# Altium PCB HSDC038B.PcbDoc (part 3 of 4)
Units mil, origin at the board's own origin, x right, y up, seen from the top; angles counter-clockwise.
Board outline 3620 x 4060 mil, 6 copper layers (Top Layer, Signal Layer 1, Signal Layer 2, Signal Layer 3, Signal Layer 4, Bottom Layer), stack 60.4 mil thick; 349 components, 209 nets, 1023 pads, 960 vias.
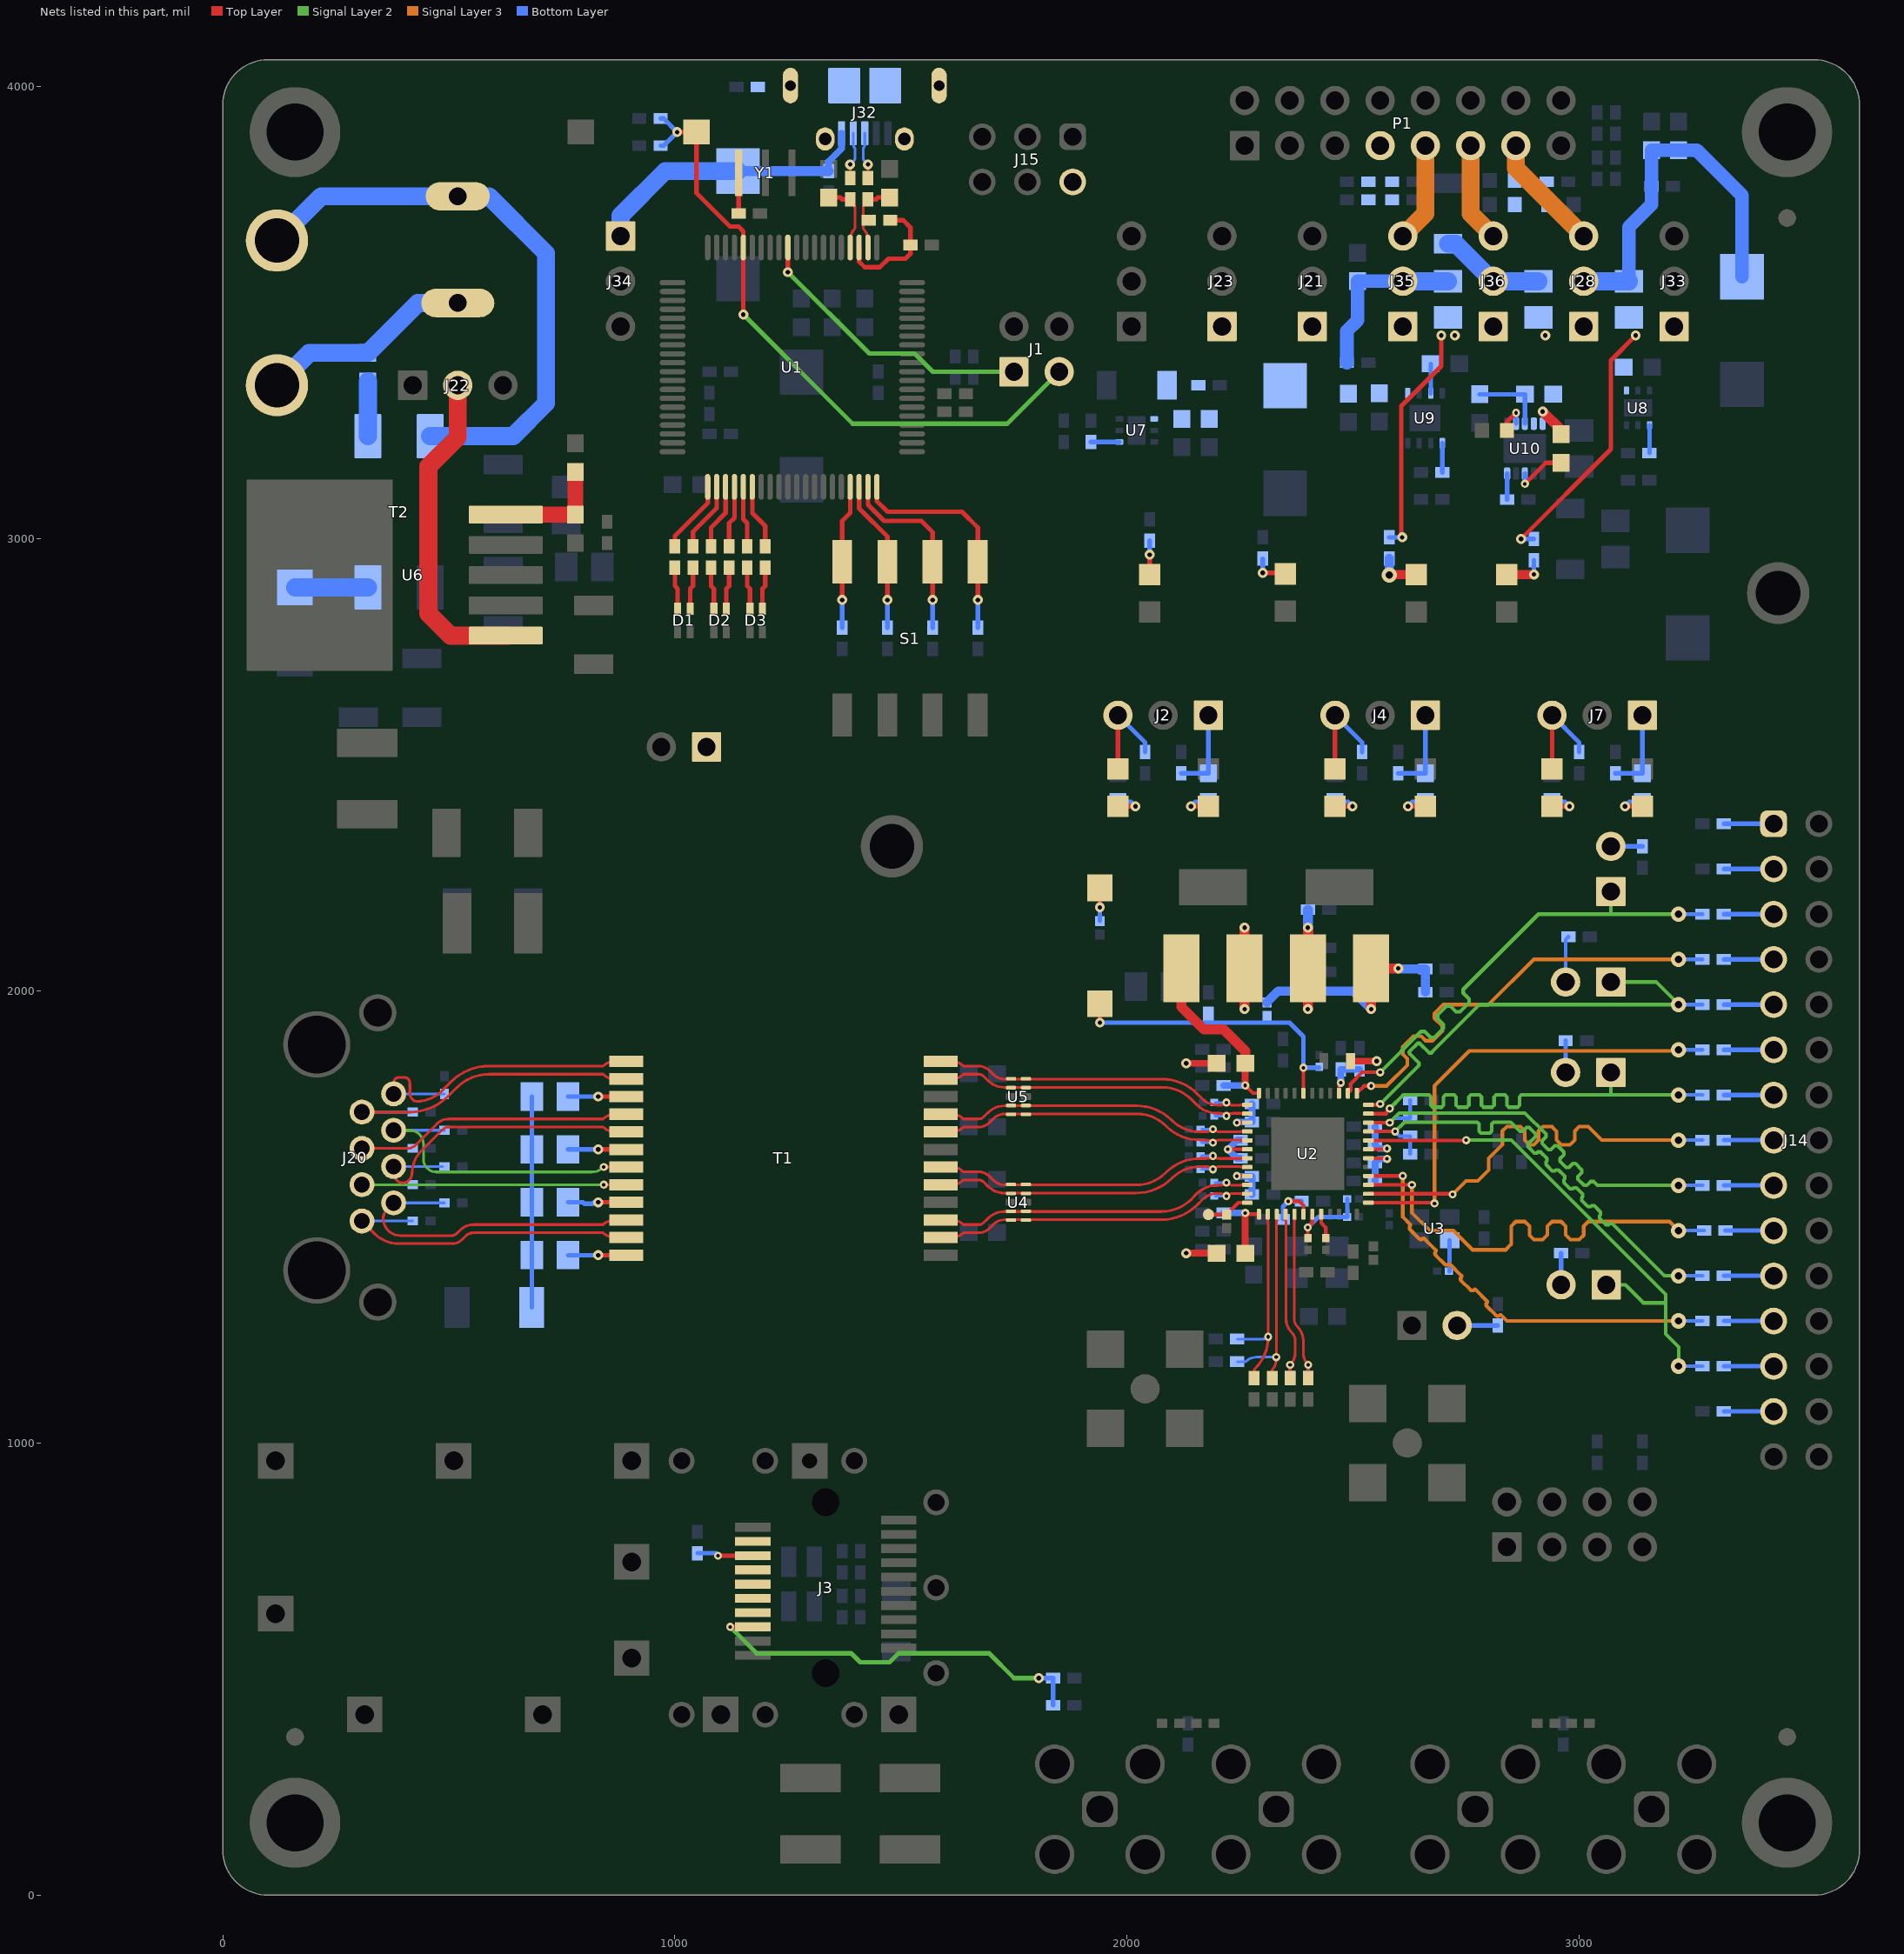
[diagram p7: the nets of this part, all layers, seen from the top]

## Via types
v1: diameter 24, hole 12, Top Layer to Bottom Layer, tented both sides, 728 vias
v2: diameter 22, hole 10, Top Layer to Bottom Layer, tented both sides, 113 vias
v3: diameter 17.87, hole 7.87, Top Layer to Bottom Layer, tented both sides, 67 vias
v4: diameter 19.68, hole 7.87, Top Layer to Bottom Layer, tented both sides, 24 vias
v5: diameter 34, hole 16, Top Layer to Bottom Layer, tented both sides, 15 vias
v6: diameter 18, hole 8, Top Layer to Bottom Layer, tented both sides, 13 vias

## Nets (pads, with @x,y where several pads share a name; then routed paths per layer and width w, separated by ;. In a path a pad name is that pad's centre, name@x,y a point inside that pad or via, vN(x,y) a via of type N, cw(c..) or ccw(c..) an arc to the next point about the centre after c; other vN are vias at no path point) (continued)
NetC59_1: C59.1 R96.1 R97.1 R98.1 R99.1 | length 466.4
  Bottom Layer w10: C59.1@683.61,1300 R99.1@683.61,1415.63 R98.1@683.61,1532.56 R97.1@683.61,1649.49 R96.1@683.61,1766.42
NetC88_2: C88.2 C89.2 C90.2 C91.1 J28.2 R105.1 | length 832.1
  Bottom Layer w30: R105.1@3110,3570 3110,3690 3160,3740 C90.2@3160,3780 C89.2@3160,3860 C88.2@3220,3860 3260,3860 3360,3760 C91.1@3360,3580
  Bottom Layer w40: J28.2@3010,3570 R105.1@3110,3570
NetC98_1: C98.1 C100.2 C101.2 C102.2 J35.2 R111.1 | length 389.8
  Bottom Layer w30: C102.2@2486.38,3390 2486.38,3460 2510,3483.62 C101.2@2510,3570 J35.2@2610,3570
  Bottom Layer w40: J35.2@2610,3570 R111.1@2710,3570
NetC105_2: C105.2 U9.3 | length 64.9
  Bottom Layer w10: U9.3@2671.85,3322.4 C105.2@2671.85,3387.28
NetC110_1: C110.1 C111.1 C112.2 C113.2 C114.2 J36.2 R115.1 | length 234.4
  Bottom Layer w40: C110.1@2710,3653.07 2726.93,3653.07 J36.2@2810,3570 R115.1@2910,3570
NetC118_2: C118.2 U10.7 | length 71.2
  Top Layer w10: C118.2@2840.32,3240 2840.32,3259 v3(2860.32,3279)
  Bottom Layer w10: U10.7@2860.31,3255.12 v3(2860.32,3279)
NetD1_1: D1.1 R2.1 | length 93.4
  Top Layer w10: D1.1@1033.78,2845.59 1033.78,2890 1040,2896.22 R2.1@1040,2936.38
NetD1_2: D1.2 R1.1 | length 93.4
  Top Layer w10: R1.1@1000,2936.38 1000,2896.22 1006.22,2890 D1.2@1006.22,2845.59
NetD2_1: D2.1 R4.1 | length 93.4
  Top Layer w10: D2.1@1113.78,2845.59 1113.78,2890 1120,2896.22 R4.1@1120,2936.38
NetD2_2: D2.2 R3.1 | length 93.4
  Top Layer w10: R3.1@1080,2936.38 1080,2896.22 1086.22,2890 D2.2@1086.22,2845.59
NetD3_1: D3.1 R6.1 | length 93.4
  Top Layer w10: D3.1@1193.78,2845.59 1193.78,2890 1200,2896.22 R6.1@1200,2936.38
NetD3_2: D3.2 R5.1 | length 93.4
  Top Layer w10: R5.1@1160,2936.38 1160,2896.22 1166.22,2890 D3.2@1166.22,2845.59
NetD4_2: D4.2 T2.4 | length 161.1
  Bottom Layer w40: D4.2@160,2892.68 T2.4@321.1,2892.68
NetD5_1: D5.1 R107.1 | length 75.1
  Top Layer w10: D5.1@2050,2921.32 v2(2050,2965)
  Bottom Layer w10: v2(2050,2965) R107.1@2050,2996.38
NetD6_1: D6.1 R108.1 | length 82.3
  Top Layer w10: v2(2300,2924.98) 2347.66,2924.98 D6.1@2350,2922.64
  Bottom Layer w10: v2(2300,2924.98) R108.1@2300,2956.38
NetD7_1: D7.1 R109.1 | length 96.9
  Top Layer w20: v5(2580,2920) 2581.34,2921.34 D7.1@2640,2921.34
  Bottom Layer w20: v5(2580,2920) R109.1@2580,2956.38
NetD8_1: D8.1 R110.1 | length 91.4
  Top Layer w20: D8.1@2840,2921.34 v2(2900,2921.34)
  Bottom Layer w10: v2(2900,2921.34) R110.1@2900,2952.71
NetF1_1: F1.1 J24.1 J25.1 | length 475.3
  Bottom Layer w40: J24.1@120,3340 191.5,3411.5 F1.1@321.1,3411.5 431.5,3521.89 J25.1@520,3521.89
NetF1_2: F1.2 T2.1 | length 121.2
  Bottom Layer w40: T2.1@321.1,3227.32 F1.2@321.1,3348.5
NetJ2_1: J2.1 R20.2 R21.1 | length 188.5
  Bottom Layer w10: R20.2@2120,2481.5 R21.1@2180,2481.5 J2.1@2180,2610
NetJ2_3: J2.3 LD1.2 R19.1 | length 224.8
  Top Layer w10: LD1.2@1980,2491.34 J2.3@1980,2610
  Bottom Layer w10: J2.3@1980,2610 2040,2550 R19.1@2040,2528.74
NetJ4_1: J4.1 R27.2 R28.2 | length 188.5
  Bottom Layer w10: R27.2@2600,2481.5 R28.2@2660,2481.5 J4.1@2660,2610
NetJ4_3: J4.3 LD3.2 R25.1 | length 224.8
  Top Layer w10: LD3.2@2460,2491.34 J4.3@2460,2610
  Bottom Layer w10: J4.3@2460,2610 2520,2550 R25.1@2520,2528.74
NetJ6_2: J6.2 R30.1 | length 70
  Bottom Layer w10: J6.2@2960,1350 R30.1@2960,1420
NetJ7_1: J7.1 R36.2 R37.2 | length 188.5
  Bottom Layer w10: R37.2@3080,2481.5 R36.2@3140,2481.5 J7.1@3140,2610
NetJ7_3: J7.3 LD5.2 R32.1 | length 224.8
  Top Layer w10: LD5.2@2940,2491.34 J7.3@2940,2610
  Bottom Layer w10: J7.3@2940,2610 3000,2550 R32.1@3000,2528.74
NetJ8_2: J8.2 R35.1 | length 70
  Bottom Layer w10: J8.2@3070,2320 R35.1@3140,2320
NetJ10_2: J10.2 R42.1 | length 70
  Bottom Layer w10: J10.2@2970,1820 R42.1@2970,1890
NetJ11_2: J11.2 R44.1 | length 102.6
  Bottom Layer w8: J11.2@2970,2020 2970,2113.62 R44.1@2976.38,2120
NetJ14_1: J14.1 R49.1 | length 110
  Bottom Layer w10: R49.1@3320,2370 J14.1@3430,2370
NetJ14_3: J14.3 R50.1 | length 110
  Bottom Layer w10: R50.1@3320,2270 J14.3@3430,2270
NetJ14_5: J14.5 R51.1 | length 110
  Bottom Layer w10: R51.1@3320,2170 J14.5@3430,2170
NetJ14_7: J14.7 R52.1 | length 110
  Bottom Layer w10: R52.1@3320,2070 J14.7@3430,2070
NetJ14_9: J14.9 R53.1 | length 110
  Bottom Layer w10: R53.1@3320,1970 J14.9@3430,1970
NetJ14_11: J14.11 R54.1 | length 110
  Bottom Layer w10: R54.1@3320,1870 J14.11@3430,1870
NetJ14_13: J14.13 R55.1 | length 110
  Bottom Layer w10: R55.1@3320,1770 J14.13@3430,1770
NetJ14_15: J14.15 R56.1 | length 110
  Bottom Layer w10: R56.1@3320,1670 J14.15@3430,1670
NetJ14_17: J14.17 R57.1 | length 110
  Bottom Layer w10: R57.1@3320,1570 J14.17@3430,1570
NetJ14_19: J14.19 R58.1 | length 106.4
  Bottom Layer w10: R58.1@3323.62,1470 J14.19@3430,1470
NetJ14_21: J14.21 R59.1 | length 110
  Bottom Layer w10: R59.1@3320,1370 J14.21@3430,1370
NetJ14_23: J14.23 R60.1 | length 110
  Bottom Layer w10: R60.1@3320,1270 J14.23@3430,1270
NetJ14_25: J14.25 R61.1 | length 110
  Bottom Layer w10: R61.1@3320,1170 J14.25@3430,1170
NetJ14_27: J14.27 R62.1 | length 110
  Bottom Layer w10: R62.1@3320,1070 J14.27@3430,1070
NetJ19_2: J19.2 R93.1 | length 90
  Bottom Layer w10: J19.2@2730,1260 R93.1@2820,1260
NetJ22_2: J22.2 U6.1 | length 728.2
  Top Layer w40: J22.2@520,3340 520,3225 455,3160 455,2835 503.86,2786.14 U6.1@631.06,2786.14
NetJ25_2: J25.2 J29.1 T2.2 | length 1306.1
  Bottom Layer w40: J29.1@120,3660 218.11,3758.11 J25.2@520,3758.11 588.89,3758.11 715,3632 715,3300 642.32,3227.32 T2.2@458.9,3227.32
NetJ32_6: J32.6 J32.7 J32.8 J32.9 J32.10 J32.11 R112.1
NetLD1_1: LD1.1 R18.2 | length 81.4
  Top Layer w10: LD1.1@1980,2408.66 v2(2018.66,2408.66)
  Bottom Layer w10: R18.2@1980,2418.5 2008.82,2418.5 v2(2018.66,2408.66)
NetLD2_1: LD2.1 R21.2 | length 81.4
  Top Layer w10: v2(2141.34,2408.66) LD2.1@2180,2408.66
  Bottom Layer w10: v2(2141.34,2408.66) 2151.18,2418.5 R21.2@2180,2418.5
NetLD3_1: LD3.1 R24.2 | length 81.4
  Top Layer w10: LD3.1@2460,2408.66 v2(2498.66,2408.66)
  Bottom Layer w10: R24.2@2460,2418.5 2488.82,2418.5 v2(2498.66,2408.66)
NetLD4_1: LD4.1 R28.1 | length 81.4
  Top Layer w10: v2(2621.34,2408.66) LD4.1@2660,2408.66
  Bottom Layer w10: v2(2621.34,2408.66) 2631.18,2418.5 R28.1@2660,2418.5
NetLD5_1: LD5.1 R29.2 | length 81.4
  Top Layer w10: LD5.1@2940,2408.66 v2(2978.66,2408.66)
  Bottom Layer w10: R29.2@2940,2418.5 2968.82,2418.5 v2(2978.66,2408.66)
NetLD6_1: LD6.1 R36.1 | length 81.4
  Top Layer w10: v2(3101.34,2408.66) LD6.1@3140,2408.66
  Bottom Layer w10: v2(3101.34,2408.66) 3111.18,2418.5 R36.1@3140,2418.5
NetR11_1: R11.1 Y1.3 | length 90
  Top Layer w10: R11.1@1141.14,3720 Y1.3@1141.14,3810
NetR80_2: R80.2 S3.2 | length 73
  Top Layer w10: v2(1940,2185) S3.2@1940,2227.95
  Bottom Layer w10: R80.2@1940,2154.96 v2(1940,2185)
NetR87_1: R87.1 U3.1 | length 68.8
  Bottom Layer w10: R87.1@2713.46,1380 U3.1@2713.46,1448.82
NetR96_2: R96.2 T1.15 | length 128.8
  Top Layer w10: v2(830.63,1766.42) T1.15@892.46,1766.42
  Bottom Layer w10: R96.2@763.61,1766.42 v2(830.63,1766.42)
NetR97_2: R97.2 T1.18 | length 128.8
  Top Layer w10: v2(830.63,1649.49) T1.18@892.46,1649.49
  Bottom Layer w10: R97.2@763.61,1649.49 v2(830.63,1649.49)
NetR98_2: R98.2 T1.21 | length 131.6
  Top Layer w10: v2(830.63,1532.56) T1.21@892.46,1532.56
  Bottom Layer w10: R98.2@763.61,1532.56 796.6,1532.56 799.97,1529.19 818.03,1529.19 821.4,1532.56 v2(830.63,1532.56)
NetR99_2: R99.2 T1.24 | length 128.8
  Top Layer w10: v2(830.63,1415.63) T1.24@892.46,1415.63
  Bottom Layer w10: R99.2@763.61,1415.63 v2(830.63,1415.63)
NetR102_1: R102.1 R103.2 U6.5 | length 248.6
  Top Layer w35: U6.5@626.06,3053.86 R102.1@780,3053.86 R103.2@780,3148.5
NetR104_1: R104.1 U7.4 | length 63.2
  Bottom Layer w10: R104.1@1920,3214.41 U7.4@1983.23,3214.41
NetR106_1: R106.1 U8.4 | length 61.6
  Bottom Layer w10: R106.1@3155.59,3190 U8.4@3155.59,3251.61
NetR113_1: R113.1 U9.5 | length 64.9
  Bottom Layer w10: R113.1@2697.44,3147.28 U9.5@2697.44,3212.17
NetR114_2: R114.2 U10.3 | length 122.1
  Top Layer w10: v3(2880,3122) 2926.5,3168.5 R114.2@2960,3168.5
  Bottom Layer w10: v3(2880,3122) U10.3@2880,3144.88
NetR116_2: R116.2 U10.5 | length 58
  Bottom Layer w10: R116.2@2840.63,3086.93 U10.5@2840.63,3144.88
NetR117_1: R117.1 R120.2 U10.8 | length 164.9
  Bottom Layer w10: R120.2@2780,3320 R117.1@2880,3320 U10.8@2880,3255.12
P1.0: R1.2 U1.21 | length 161.8
  Top Layer w10: R1.2@1000,2983.62 1000,3006.81 1072.76,3079.57 U1.21@1072.76,3115.24
P1.1: R2.2 U1.22 | length 153.3
  Top Layer w10: R2.2@1040,2983.62 1040,3015.74 1092.44,3068.19 U1.22@1092.44,3115.24
P1.2: R3.2 U1.23 | length 144.9
  Top Layer w10: R3.2@1080,2983.62 1080,3025 1112.13,3057.13 U1.23@1112.13,3115.24
P1.3: R4.2 U1.24 | length 136.5
  Top Layer w10: R4.2@1120,2983.62 1120,3035 1131.81,3046.81 U1.24@1131.81,3115.24
P1.4: R5.2 U1.25 | length 135.1
  Top Layer w10: U1.25@1151.5,3115.24 1151.5,3043.5 1160,3035 R5.2@1160,2983.62
P1.5: R6.2 U1.26 | length 143.6
  Top Layer w10: U1.26@1171.18,3115.24 1171.18,3057.32 1200,3028.5 R6.2@1200,2983.62
RBIAS: R73.2 TP7.1 U2.12 | length 97
  Top Layer w8: TP7.1@2180,1505.45 R73.2@2220,1505.45 2246.28,1531.73 U2.12@2266.14,1531.73
RESET_N: R77.1 R82.2 R83.2 S3.1 U2.43 | length 665
  Top Layer w8: U2.43@2390.16,1773.86 v3(2390.16,1830.31)
  Top Layer w10: v2(1940,1930) S3.1@1940,1972.05
  Bottom Layer w10: v2(1940,1930) 2359.07,1930 2390.16,1898.91 v3(2390.16,1830.31) R83.2@2425,1830.31
RST/SBWTDIO: C1.2 J1.3 R12.2 S2.2 U1.76 | length 1444.3
  Top Layer w10: v2(1005,3900) S2.2@1047.95,3900 1047.95,3765.05 1122,3691 1141,3691 1151.5,3680.5 U1.76@1151.5,3644.76 v2(1151.5,3496.5)
  Signal Layer 2 w10: v2(1151.5,3496.5) 1393,3255 1735,3255 J1.3@1850,3370
  Bottom Layer w10: R12.2@968.62,3870 975,3870 v2(1005,3900) 975,3930 C1.2@968.62,3930
RX_CLK: J6.1 R61.2 U2.32 | length 1169.4
  Top Layer w8: U2.32@2533.86,1669.53 v6@2749.53,1669.53
  Signal Layer 2 w8: v6(2750,1670) 2850,1670 3191.13,1328.87 3191.13,1310 ; J6.1@3060,1350 3102.43,1350 3142.43,1310 3191.13,1310 ; v5(3220,1170) 3220,1212.25 3191.13,1241.13 3191.13,1310
  Bottom Layer w8: v5(3220,1170) R61.2@3272.76,1170
RX_CTRL: J8.1 R51.2 U2.38 | length 1108
  Top Layer w8: U2.38@2488.58,1773.86 2494.53,1779.8 2494.53,1794.53 2520,1820 v6(2560,1820)
  Signal Layer 2 w8: v6(2560,1820) 2650.19,1910.19 2658.68,1910.19 2671.41,1897.47 2679.89,1897.47 2699.69,1917.26 2699.69,1925.75 2686.96,1938.48 2686.96,1946.96 2706.76,1966.76 2715.25,1966.76 2727.98,1954.03 2736.46,1954.03 2756.26,1973.83 2756.26,1982.32 2743.53,1995.05 2743.53,2003.53 2910,2170 3070,2170 ; J8.1@3076.5,2213.5 J8.1@3070,2220 3070,2170 ; v5(3220,2170) 3070,2170
  Bottom Layer w8: v5(3220,2170) R51.2@3272.76,2170
RX_D0: R33.1 R41.2 R59.2 U2.33 | length 1104
  Top Layer w8: U2.33@2533.86,1689.21 v3(2593,1689.21)
  Signal Layer 2 w8: v3(2593,1689.21) 2613.68,1709.9 2774.33,1709.9 2778.53,1705.7 2778.53,1690.07 2782.73,1685.87 2802.33,1685.87 2806.53,1690.07 2806.53,1705.7 2810.73,1709.9 2848.53,1709.9 2869.14,1689.28 2875.08,1689.28 2883.7,1697.91 2889.64,1697.91 2903.5,1684.05 2903.5,1678.11 2886.89,1661.5 2886.89,1655.56 2900.75,1641.7 2906.69,1641.7 2908.74,1643.75 2914.68,1643.75 2928.54,1629.89 2928.54,1623.95 2926.49,1621.9 2926.49,1615.96 2940.35,1602.1 2946.29,1602.1 2948.34,1604.15 2954.28,1604.15 2968.14,1590.29 2968.14,1584.35 2966.09,1582.3 2966.09,1576.36 2979.95,1562.5 2985.89,1562.5 2987.93,1564.55 2993.87,1564.55 3007.73,1550.69 3007.73,1544.75 3005.68,1542.7 3005.68,1536.76 3019.54,1522.9 3025.48,1522.9 3027.53,1524.95 3033.47,1524.95 3047.33,1511.09 3047.33,1505.15 3045.28,1503.1 3045.28,1497.16 3059.14,1483.31 3065.08,1483.31 3067.13,1485.35 3073.07,1485.35 3188.43,1370 v5(3220,1370)
  Bottom Layer w8: v3(2593,1689.21) 2603,1679.21 R33.1@2626.38,1679.21 R41.2@2626.38,1639.21 ; v5(3220,1370) R59.2@3272.76,1370
RX_D1: R40.1 R43.2 R57.2 U2.34 | length 997.5
  Top Layer w8: U2.34@2533.86,1708.9 v3(2581,1708.9)
  Signal Layer 2 w8: v3(2581,1708.9) 2602.1,1730 2880,1730 2926.53,1683.47 2926.53,1677.53 2917.9,1668.91 2917.9,1662.97 2931.76,1649.11 2937.7,1649.11 2946.33,1657.73 2952.27,1657.73 2966.13,1643.87 2966.13,1637.93 2957.5,1629.31 2957.5,1623.37 2971.36,1609.51 2977.3,1609.51 2985.92,1618.14 2991.86,1618.14 3005.72,1604.28 3005.72,1598.34 2997.1,1589.71 2997.1,1583.77 3010.96,1569.91 3016.9,1569.91 3025.52,1578.54 3031.46,1578.54 3040,1570 v5(3220,1570)
  Bottom Layer w8: v3(2581,1708.9) 2591,1718.9 R40.1@2626.38,1718.9 R43.2@2626.38,1758.9 ; v5(3220,1570) R57.2@3272.76,1570
RX_D2: J10.1 R55.2 U2.35 | length 989
  Top Layer w8: U2.35@2533.86,1728.58 2573.58,1728.58 2573.58,1732.58 v6(2581,1740)
  Signal Layer 2 w8: v6@2581,1736 v6(2581,1740) 2611,1770 2667.8,1770 2672,1765.8 2672,1747.2 2676.2,1743 2695.8,1743 2700,1747.2 2700,1765.8 2704.2,1770 2723.8,1770 2728,1765.8 2728,1747.2 2732.2,1743 2751.8,1743 2756,1747.2 2756,1765.8 2760.2,1770 2779.8,1770 2784,1765.8 2784,1747.2 2788.2,1743 2807.8,1743 2812,1747.2 2812,1765.8 2816.2,1770 2835.8,1770 2840,1765.8 2840,1747.2 2844.2,1743 2863.8,1743 2868,1747.2 2868,1765.8 2872.2,1770 3070,1770 ; J10.1@3070,1820 3070,1770 ; v5(3220,1770) 3070,1770
  Bottom Layer w8: v5(3220,1770) R55.2@3272.76,1770
RX_D3: J11.1 R53.2 U2.36 | length 1066.4
  Top Layer w8: U2.36@2533.86,1748.27 2558.27,1748.27 v6(2560,1750)
  Signal Layer 2 w8: v6(2560,1750) 2644.78,1834.78 ccw(c2641.39,1838.18) 2644.79,1841.56 2625.76,1860.59 cw(c2629.16,1863.99) 2625.76,1867.38 2641.6,1883.22 ; 2641.61,1883.23 cw(c2645,1879.82) 2648.38,1883.23 ; 2648.39,1883.22 2667.41,1864.2 ccw(c2670.8,1867.59) 2674.19,1864.19 2780,1970 v5(3220,1970) 3170,2020 J11.1@3070,2020
  Bottom Layer w8: v5(3220,1970) R53.2@3272.76,1970
SFP_LOS: J3.8 R22.1 R23.2 | length 887.5
  Top Layer w10: v3(1122.36,593.39) J3.8@1172.28,593.39
  Signal Layer 2 w10: v3(1122.36,593.39) 1180.75,535 1390,535 1410,515 1475,515 1495,535 1695,535 1750,480 v2(1805,480)
  Bottom Layer w10: v2(1805,480) R22.1@1836.38,480 R23.2@1836.38,420
SFP_MD_0: J3.6
SFP_MD_1: J3.5
SFP_MD_2: J3.4
SFP_RS: J3.7
SFP_TX_DISABLE: J3.3 R26.2 | length 124.6
  Top Layer w10: v6(1095.51,750.87) J3.3@1172.28,750.87
  Bottom Layer w10: R26.2@1050,756.38 1090,756.38 v6(1095.51,750.87)
SFP_TX_FAULT: J3.2
SGMII_SI_N: C15.2 R45.1 U2.17 | length 400.6
  Top Layer w6: U2.17@2370.47,1506.14 2370.47,1492.52 cw(c2367.6,1492.52) 2369.63,1490.49 2369.63,1274.86 ccw(c2393.86,1274.86) 2376.73,1257.73 cw(c2345.2,1226.2) 2389.79,1226.2 2389.79,1199.66 ccw(c2427.34,1199.66) v3(2400.79,1173.1) C15.2@2400.79,1143.62
  Bottom Layer w6: R45.1@2400.79,1143.62 v3(2400.79,1173.1)
SGMII_SI_P: C17.2 R47.1 U2.16 | length 400.6
  Top Layer w6: U2.16@2350.79,1506.14 2350.79,1492.52 ccw(c2353.66,1492.52) 2351.63,1490.49 2351.63,1274.86 ccw(c2393.86,1274.86) 2364,1245 cw(c2345.2,1226.2) 2371.79,1226.2 2371.79,1199.66 cw(c2334.23,1199.66) v3(2360.79,1173.1) C17.2@2360.79,1143.62
  Bottom Layer w6: R47.1@2360.79,1143.62 v3(2360.79,1173.1)
SGMII_SO_N: C12.2 R31.1 U2.14 | length 441.2
  Top Layer w6: C12.2@2281.1,1143.62 2281.1,1159.73 cw(c2287.48,1159.73) 2282.97,1164.24 ccw(c2212.26,1234.95) v6(2312.26,1234.95) 2312.26,1490.49 2311.42,1491.33 U2.14@2311.42,1506.14
  Bottom Layer w6: R31.1@2243.62,1230 2300.31,1230 ccw(c2300.31,1246.9) v6(2312.26,1234.95)
SGMII_SO_P: C14.2 R38.1 U2.15 | length 454.4
  Top Layer w6: C14.2@2321.1,1143.62 2321.1,1162.37 ccw(c2298.99,1184.48) 2330.26,1184.48 2330.26,1490.49 2331.1,1491.33 U2.15@2331.1,1506.14
  Bottom Layer w6: R38.1@2243.62,1180 2262.37,1180 cw(c2286.51,1155.86) 2286.51,1190 v6(2330,1190)
SW_1: R10.2 S1.4 U1.37 | length 319
  Top Layer w10: v2(1370,2865) S1.4@1370,2949.5 1370,3040 1387.72,3057.72 U1.37@1387.72,3115.24
  Bottom Layer w10: R10.2@1370,2803.62 v2(1370,2865)
SW_2: R9.2 S1.3 U1.38 | length 337.5
  Top Layer w10: U1.38@1407.4,3115.24 1407.4,3067.6 1470,3005 S1.3@1470,2949.5 v2(1470,2865)
  Bottom Layer w10: R9.2@1470,2803.62 v2(1470,2865)
SW_3: R8.2 S1.2 U1.39 | length 419
  Top Layer w10: U1.39@1427.09,3115.24 1427.09,3075.63 1462.72,3040 1545,3040 1570,3015 S1.2@1570,2949.5 v2(1570,2865)
  Bottom Layer w10: R8.2@1570,2803.62 v2(1570,2865)
SW_4: R7.2 S1.1 U1.40 | length 500.5
  Top Layer w10: U1.40@1446.77,3115.24 1446.77,3083.54 1470.31,3060 1635,3060 1670,3025 S1.1@1670,2949.5 v2(1670,2865)
  Bottom Layer w10: R7.2@1670,2803.62 v2(1670,2865)
TARGET_D_N: C11.2 R16.1 U1.64 | length 162
  Top Layer w6: U1.64@1387.72,3644.76 1387.72,3661.2 cw(c1424.2,3661.2) 1398.4,3686.99 1398.4,3729.82 ccw(c1372.17,3729.82) 1390.72,3748.38 R16.1@1387.72,3751.38
  Top Layer w10: C11.2@1340.2,3755.49 1365.71,3755.49 1369.82,3751.38 R16.1@1387.72,3751.38
TARGET_D_P: C10.2 R13.2 R17.1 U1.62 | length 162
  Top Layer w6: U1.62@1427.09,3644.76 1427.09,3661.2 ccw(c1390.61,3661.2) 1416.4,3686.99 1416.4,3729.82 cw(c1442.64,3729.82) 1424.09,3748.38 R17.1@1427.09,3751.38
  Top Layer w10: R17.1@1427.09,3751.38 1444.99,3751.38 1449.09,3755.49 C10.2@1474.61,3755.49
TARGET_PUR: R13.1 R14.1 U1.63 | length 271.9
  Top Layer w10: U1.63@1407.4,3644.76 1407.4,3613.6 1420,3601 1453.4,3601 1472.4,3620 1510.2,3620 1520.91,3630.71 R14.1@1520.91,3650 1520.91,3689.29 1505.2,3705 R13.1@1476.33,3705
TD_A_N: R64.1 T1.11 U2.2 U5.2 U5.9 | length 736
  Top Layer w6: T1.11@1587.54,1805.39 1613.21,1805.39 ccw(c1613.21,1841.2) 1638.53,1815.88 1671.74,1815.88 cw(c1671.74,1799.58) 1683.27,1811.11 1692.37,1802.01 ccw(c1728.6,1838.23) 1728.6,1787 2077.75,1787 cw(c2077.75,1695.75) 2142.27,1760.27 2154.11,1748.43 ccw(c2200,1794.32) 2200,1729.43 2205.89,1729.43 cw(c2205.89,1709.48) v3(2220,1723.58) cw(c2234.11,1709.48) 2234.11,1729.43 2250.49,1729.43 ccw(c2252.52,1731.46) 2252.52,1728.58 U2.2@2266.14,1728.58
  Bottom Layer w6: R64.1@2194.96,1723.58 v3(2220,1723.58)
TD_A_P: R63.1 T1.12 U2.1 U5.1 U5.10 | length 736
  Top Layer w6: T1.12@1587.54,1844.37 1613.21,1844.37 cw(c1613.21,1808.56) 1638.53,1833.88 1671.74,1833.88 cw(c1671.74,1799.58) 1696,1823.83 1705.1,1814.73 ccw(c1728.6,1838.23) 1728.6,1805 2077.75,1805 cw(c2077.75,1695.75) 2155,1773 2166.84,1761.16 ccw(c2200,1794.32) 2200,1747.43 2205.89,1747.43 ccw(c2205.89,1767.37) v3(2220,1753.27) ccw(c2234.11,1767.37) 2234.11,1747.43 2250.49,1747.43 cw(c2252.52,1745.39) 2252.52,1748.27 U2.1@2266.14,1748.27
  Bottom Layer w6: R63.1@2194.96,1753.27 v3(2220,1753.27)
TD_B_N: R66.1 T1.8 U2.5 U5.5 U5.6 | length 734.3
  Top Layer w6: T1.8@1587.54,1688.46 1613.21,1688.46 ccw(c1613.21,1724.27) 1638.53,1698.95 1671.74,1698.95 ccw(c1671.74,1733.26) 1696,1709 1705.1,1718.1 cw(c1729,1694.2) 1729,1728 2021.75,1728 cw(c2021.75,1636.75) 2086.27,1701.27 ccw(c2160.88,1775.88) 2160.88,1670.37 2175.89,1670.37 cw(c2175.89,1650.42) v3(2190,1664.53) cw(c2204.11,1650.42) 2204.11,1670.37 2250.49,1670.37 ccw(c2252.52,1672.4) 2252.52,1669.53 U2.5@2266.14,1669.53
  Bottom Layer w6: R66.1@2164.96,1664.53 v3(2190,1664.53)
TD_B_P: R65.1 T1.9 U2.4 U5.4 U5.7 | length 734.3
  Top Layer w6: T1.9@1587.54,1727.44 1613.21,1727.44 cw(c1613.21,1691.63) 1638.53,1716.95 1671.74,1716.95 ccw(c1671.74,1733.26) 1683.27,1721.73 1692.37,1730.83 cw(c1729,1694.2) 1729,1746 2021.75,1746 cw(c2021.75,1636.75) 2099,1714 ccw(c2160.88,1775.88) 2160.88,1688.37 2175.89,1688.37 ccw(c2175.89,1708.32) v3(2190,1694.21) ccw(c2204.11,1708.32) 2204.11,1688.37 2250.49,1688.37 cw(c2252.52,1686.34) 2252.52,1689.21 U2.4@2266.14,1689.21
  Bottom Layer w6: R65.1@2164.96,1694.21 v3(2190,1694.21)
TD_C_N: R68.1 T1.5 U2.8 U4.2 U4.9 | length 734.5
  Top Layer w6: T1.5@1587.54,1571.54 1613.21,1571.54 ccw(c1613.21,1607.34) 1638.53,1582.02 1671.74,1582.02 cw(c1671.74,1565.72) 1683.27,1577.25 1692.37,1568.15 ccw(c1728.94,1604.72) 1728.94,1553 2020.09,1553 ccw(c2020.09,1664.59) 2099,1585.69 cw(c2160.88,1523.81) 2160.88,1611.32 2175.89,1611.32 cw(c2175.89,1591.37) v3(2190,1605.47) cw(c2204.11,1591.37) 2204.11,1611.32 2250.49,1611.32 ccw(c2252.52,1613.35) 2252.52,1610.47 U2.8@2266.14,1610.47
  Bottom Layer w6: R68.1@2164.96,1605.47 v3(2190,1605.47)
TD_C_P: R67.1 T1.6 U2.7 U4.1 U4.10 | length 734.5
  Top Layer w6: T1.6@1587.54,1610.51 1613.21,1610.51 cw(c1613.21,1574.7) 1638.53,1600.02 1671.74,1600.02 cw(c1671.74,1565.72) 1696,1589.98 1705.1,1580.88 ccw(c1728.94,1604.72) 1728.94,1571 2020.09,1571 ccw(c2020.09,1664.59) 2086.27,1598.41 cw(c2160.88,1523.81) 2160.88,1629.32 2175.89,1629.32 ccw(c2175.89,1649.26) v3(2190,1635.16) ccw(c2204.11,1649.26) 2204.11,1629.31 2250.49,1629.32 cw(c2252.52,1627.28) 2252.52,1630.16 U2.7@2266.14,1630.16
  Bottom Layer w6: R67.1@2164.96,1635.16 v3(2190,1635.16)
TD_D_N: R70.1 T1.2 U2.11 U4.5 U4.6 | length 736.2
  Top Layer w6: T1.2@1587.54,1454.61 1613.21,1454.61 ccw(c1613.21,1490.42) 1638.53,1465.09 1671.74,1465.09 ccw(c1671.74,1499.4) 1696,1475.14 1705.1,1484.24 cw(c1728.66,1460.69) 1728.66,1494 2076.09,1494 ccw(c2076.09,1605.59) 2155,1526.69 2166.84,1538.52 cw(c2200,1505.36) 2200,1552.26 2205.89,1552.26 cw(c2205.89,1532.31) v3(2220,1546.42) cw(c2234.11,1532.31) 2234.11,1552.26 2250.49,1552.26 ccw(c2252.52,1554.29) 2252.52,1551.42 U2.11@2266.14,1551.42
  Bottom Layer w6: R70.1@2194.96,1546.42 v3(2220,1546.42)
TD_D_P: R69.1 T1.3 U2.10 U4.4 U4.7 | length 736.2
  Top Layer w6: T1.3@1587.54,1493.58 1613.21,1493.58 cw(c1613.21,1457.77) 1638.53,1483.09 1671.74,1483.09 ccw(c1671.74,1499.4) 1683.27,1487.87 1692.37,1496.97 cw(c1728.66,1460.69) 1728.66,1512 2076.09,1512 ccw(c2076.09,1605.59) 2142.27,1539.41 2154.11,1551.25 cw(c2200,1505.36) 2200,1570.26 2205.89,1570.26 ccw(c2205.89,1590.21) v3(2220,1576.1) ccw(c2234.11,1590.21) 2234.11,1570.26 2250.49,1570.26 cw(c2252.52,1568.23) 2252.52,1571.1 U2.10@2266.14,1571.1
  Bottom Layer w6: R69.1@2194.96,1576.1 v3(2220,1576.1)
TEST/SBWTCK: J1.1 U1.71 | length 646
  Top Layer w10: v2(1249.92,3590.08) U1.71@1249.92,3644.76
  Signal Layer 2 w10: v2(1249.92,3590.08) 1430,3410 1530.32,3410 1570.32,3370 J1.1@1750,3370
  Bottom Layer w10: v2(1249.92,3590.08) v2@1250,3590
TP_CH1_N: C56.1 J20.7 T1.14 | length 725
  Top Layer w6: J20.7@307.91,1732.17 414.74,1732.17 ccw(c414.74,1850.17) 498.18,1766.72 518.05,1786.59 cw(c588.76,1715.88) 588.76,1815.88 841.47,1815.88 ccw(c866.79,1841.2) 866.79,1805.39 T1.14@892.46,1805.39
  Bottom Layer w6: J20.7@307.91,1732.17 C56.1@420.32,1732.17
TP_CH1_P: C58.1 J20.8 T1.13 | length 725.3
  Top Layer w6: J20.8@377.99,1772.32 377.99,1796.5 cw(c390.5,1796.5) 390.5,1809 401.5,1809 cw(c401.5,1796.5) 414,1796.5 414,1773.33 ccw(c432.16,1773.33) 426.99,1755.92 428.63,1755.92 ccw(c428.63,1836.28) 485.45,1779.45 505.33,1799.33 cw(c588.76,1715.88) 588.76,1833.88 841.47,1833.88 cw(c866.79,1808.56) 866.79,1844.37 T1.13@892.46,1844.37
  Bottom Layer w6: J20.8@377.99,1772.32 C58.1@490.39,1772.32
TP_CH2_N: C53.1 J20.4 T1.17 | length 720.1
  Top Layer w6: J20.4@377.99,1611.69 377.99,1596.37 ccw(c398.35,1596.37) 398.35,1576.02 ccw(c398.35,1596.37) 418.7,1596.37 cw(c489.52,1596.37) 439.45,1646.45 486.26,1693.26 cw(c500,1679.52) 500,1698.95 841.47,1698.95 ccw(c866.79,1724.27) 866.79,1688.46 T1.17@892.46,1688.46
  Bottom Layer w6: J20.4@377.99,1611.69 C53.1@486.46,1611.69
TP_CH2_P: C55.1 J20.5 T1.16 | length 720.1
  Top Layer w6: J20.5@307.91,1651.85 408.67,1651.85 ccw(c408.67,1677.74) 426.98,1659.43 473.53,1705.99 cw(c500,1679.52) 500,1716.95 841.47,1716.95 cw(c866.79,1691.63) 866.79,1727.44 T1.16@892.46,1727.44
  Bottom Layer w6: J20.5@307.91,1651.85 C55.1@416.38,1651.85
TP_CH3_N: C50.1 J20.3 T1.20 | length 696.9
  Top Layer w6: v3(842.72,1571.54) T1.20@892.46,1571.54
  Signal Layer 2 w6: J20.3@307.91,1571.54 v3(842.72,1571.54)
  Bottom Layer w6: J20.3@307.91,1571.54 C50.1@420.32,1571.54
TP_CH3_P: C52.1 J20.6 T1.19 | length 697
  Top Layer w6: v3(842.72,1610.51) T1.19@892.46,1610.51
  Signal Layer 2 w6: J20.6@377.99,1692.01 413.26,1692.01 cw(c413.26,1661.27) 444,1661.27 444,1627.65 ccw(c472.12,1627.65) 472.12,1599.52 816.19,1599.52 ccw(c816.19,1637.04) v3(842.72,1610.51)
  Bottom Layer w6: J20.6@377.99,1692.01 C52.1@490.39,1692.01
TP_CH4_N: C47.1 J20.1 T1.23 | length 724.9
  Top Layer w6: J20.1@307.91,1491.22 335.9,1463.24 ccw(c389.58,1516.92) 389.58,1441 507.1,1441 ccw(c507.1,1473.24) 529.9,1450.44 537.73,1458.27 cw(c554.2,1441.8) 554.2,1465.09 841.47,1465.09 ccw(c866.79,1490.42) 866.79,1454.61 T1.23@892.46,1454.61
  Bottom Layer w6: J20.1@307.91,1491.22 C47.1@420.32,1491.22
TP_CH4_P: C48.1 J20.2 T1.22 | length 724.7
  Top Layer w6: J20.2@377.99,1531.38 363.05,1516.44 ccw(c382.49,1497) 355,1497 ccw(c393,1497) 393,1459 507.1,1459 ccw(c507.1,1473.24) 517.17,1463.17 525,1471 cw(c554.2,1441.8) 554.2,1483.09 841.47,1483.09 cw(c866.79,1457.77) 866.79,1493.58 T1.22@892.46,1493.58
  Bottom Layer w6: J20.2@377.99,1531.38 C48.1@490.39,1531.38
TX_CTRL: R52.2 U2.37 | length 980.6
  Top Layer w8: U2.37@2508.27,1773.86 2524.41,1790 v6(2540,1790)
  Signal Layer 3 w8: v6(2540,1790) 2574.16,1790 2620,1835.84 2620,1850 2610,1860 2610,1876.61 2633.39,1900 2650.38,1900 2660.38,1890 2675.8,1890 2697.5,1911.7 2697.5,1922.5 2680,1940 2680,1950 2700,1970 2800,1970 2900,2070 v5(3220,2070)
  Bottom Layer w8: v5(3220,2070) R52.2@3272.76,2070
TX_D0: R60.2 U2.28 | length 962.6
  Top Layer w8: U2.28@2533.86,1590.79 v6(2610,1590.79)
  Signal Layer 3 w8: v6(2610,1590.79) 2610,1500 2626.3,1483.7 cw(c2624.74,1482.13) 2626.3,1480.57 ccw(c2630.54,1476.32) 2626.3,1472.08 2646.1,1452.28 ccw(c2650.34,1456.52) 2654.59,1452.28 cw(c2656.15,1450.72) 2657.71,1452.29 2682.87,1427.13 ; 2682.88,1427.12 cw(c2681.3,1425.56) 2682.87,1424 ccw(c2687.11,1419.75) 2682.87,1415.51 2702.67,1395.71 ccw(c2706.91,1399.96) 2711.15,1395.71 cw(c2712.72,1394.15) 2714.28,1395.72 2739.44,1370.56 cw(c2737.87,1368.99) 2739.44,1367.43 ccw(c2743.68,1363.19) 2739.44,1358.94 2759.24,1339.14 ccw(c2763.48,1343.39) 2767.72,1339.14 cw(c2769.29,1337.58) 2770.85,1339.15 2796.01,1313.99 cw(c2794.44,1312.43) 2796.01,1310.86 ccw(c2800.25,1306.62) 2796.01,1302.37 2815.81,1282.58 ccw(c2820.05,1286.82) 2824.29,1282.58 cw(c2825.86,1281.01) 2827.42,1282.58 2840,1270 v5(3220,1270)
  Bottom Layer w8: v5(3220,1270) R60.2@3272.76,1270
TX_D1: R58.2 U2.27 | length 1007.9
  Top Layer w8: U2.27@2533.86,1571.1 v6(2630,1571.1)
  Signal Layer 3 w8: v6(2630,1571.1) 2630,1510 2670,1470 2721.41,1470 2764,1427.41 2837.41,1427.41 2850,1440 2850,1480 2860,1490 2880,1490 2890,1480 2890,1460 2900,1450 2919.44,1450 2930,1460.56 2930,1480 2940,1490 2960,1490 2970,1480 2970,1460.57 2980.57,1450 3000,1450 3010,1460 3010,1480 3020,1490 3200,1490 v5(3220,1470)
  Bottom Layer w8: v5(3220,1470) R58.2@3276.38,1470
TX_D2: R56.2 U2.26 | length 959.9
  Top Layer w8: U2.26@2533.86,1551.42 2718.58,1551.42 v6(2720,1550)
  Signal Layer 3 w8: v6(2720,1550) 2750,1580 2775.8,1580 2800,1604.2 2800,1630 2830,1660 2830,1690 2840,1700 2870,1700 2880,1690 2880,1670 2890,1660 2900,1660 2910,1670 2910,1690 2920,1700 2940,1700 2940,1699.21 2950,1689.21 2950,1670 2960,1660 2980,1660 2990,1670 2990,1690 3000,1700 3020,1700 3050,1670 v5(3220,1670)
  Bottom Layer w8: v5(3220,1670) R56.2@3272.76,1670
TX_D3: R54.2 U2.25 | length 1032.8
  Top Layer w8: U2.25@2533.86,1531.73 2678.27,1531.73 v6(2680,1530)
  Signal Layer 3 w8: v6(2680,1530) 2680,1790 2757.13,1867.13 3217.13,1867.13 v5(3220,1870)
  Bottom Layer w8: v5(3220,1870) R54.2@3272.76,1870
USB_N: J32.2 R16.2 | length 104
  Top Layer w6: R16.2@1387.72,3798.62 v2(1387.72,3828.57)
  Bottom Layer w6: v2(1387.72,3828.57) 1395.76,3836.61 ccw(c1389.37,3843) 1398.4,3843 1398.4,3864.23 cw(c1407.57,3873.39) 1394.61,3873.39 J32.2@1394.61,3897.6
USB_P: J32.3 R17.2 | length 104
  Top Layer w6: R17.2@1427.09,3798.62 v2(1427.09,3828.57)
  Bottom Layer w6: J32.3@1420.2,3897.6 1420.2,3873.39 cw(c1407.24,3873.39) 1416.4,3864.23 1416.4,3843 ccw(c1425.44,3843) 1419.04,3836.62 v2(1427.09,3828.57)
USB_VBUS: C92.1 C93.2 J32.1 J34.1 | length 641.8
  Bottom Layer w15: C93.2@1340,3813.62 1340,3835 1368.82,3863.82 J32.1@1368.82,3897.6
  Bottom Layer w22: C92.1@1140,3813.62 C93.2@1340,3813.62
  Bottom Layer w40: J34.1@880,3670 880,3715 978.62,3813.62 C92.1@1140,3813.62
VDDA1P0: C28.1 C29.1 C30.1 C31.1 C32.1 C33.1 C34.1 C35.1 C36.1 R115.2 TP4.1 U2.6 U2.31 U2.39 | length 640.5
  Top Layer w8: v3(2223.1,1649.84) U2.6@2266.14,1649.84 ; U2.39@2468.9,1773.86 2468.9,1792.9 v3(2472.9,1796.9) ; U2.31@2533.86,1649.84 2573.41,1649.84 v3(2575,1651.44)
  Top Layer w22: v2(2400,1960) TP4.1@2400,2050 v2(2400,2140)
  Bottom Layer w15: C33.1@2251.38,1630 2242.94,1630 v3(2223.1,1649.84) 2243.26,1670 C29.1@2251.38,1670 ; v3(2472.9,1796.9) C30.1@2472.9,1826.38 C34.1@2514,1826.38 ; C28.1@2548.62,1700 C32.1@2548.62,1660 2557.22,1651.4 v3(2575,1651.44)
  Bottom Layer w22: C35.1@2400,2042.59 C31.1@2400,2095.59 v2(2400,2140) C36.1@2400,2179.87
  other v2: 2925,3450
VDDA1P0_DUT: J36.1 R114.1 R117.2 U10.9 U10.10 | length 67.3
  Top Layer w22: v2(2919.37,3282) 2960,3241.37 R114.1@2960,3231.5
VDDA1P0_EXT: J36.3 P1.11 | length 220.7
  Signal Layer 3 w40: P1.11@2760,3870 2760,3720 J36.3@2810,3670
VDDA1P8_AB: R71.1 R118.1 U2.13 | length 168.3
  Top Layer w8: v3(2261.5,1509) 2264.35,1506.14 U2.13@2291.73,1506.14
  Top Layer w15: R118.1@2261.5,1420 v3(2261.5,1509)
  Bottom Layer w15: R71.1@2213.62,1509 v3(2261.5,1509)
VDDA1P8_CD: R72.1 R119.1 TP5.1 U2.48 | length 428.4
  Top Layer w8: v3(2261.5,1791) 2278.64,1773.86 U2.48@2291.73,1773.86
  Top Layer w15: v3(2261.5,1791) R119.1@2261.5,1840
  Top Layer w22: TP5.1@2120,2050 2120,1965 2170,1915 2213.62,1915 2261.5,1867.13 R119.1@2261.5,1840
  Bottom Layer w15: R72.1@2213.62,1791 v3(2261.5,1791)
VDDA1P8_EXT: C95.2 C97.2 C104.2 C108.2 P1.7 R118.2 R119.2 | length 135
  Top Layer w15: v2(2131,1420) R118.2@2198.5,1420 ; v2(2131,1840) R119.2@2198.5,1840
VDDA2P5: C21.1 C22.1 C26.1 C27.1 R109.2 R111.2 TP6.1 U2.3 U2.9 | length 886.1
  Top Layer w8: v3(2243.1,1590.79) U2.9@2266.14,1590.79 ; v3(2243.1,1708.9) U2.3@2266.14,1708.9
  Top Layer w10: v2(2608.62,3003.62) 2606.32,3005.92 2606.32,3293.68 2695,3382.35 v2(2695,3450)
  Top Layer w22: v2(2260,1960) TP6.1@2260,2050 v2(2260,2140)
  Bottom Layer w10: R109.2@2580,3003.62 v2(2608.62,3003.62)
  Bottom Layer w15: v3(2243.1,1590.79) 2243.89,1590 C21.1@2276.38,1590 C26.1@2276.38,1550 ; v3(2243.1,1708.9) 2244.2,1710 C27.1@2276.38,1710 C22.1@2276.38,1750
  other v2: 2725,3450
VDDA2P5_DUT: C106.2 J35.1 U9.1
VDDA2P5_EXT: J35.3 P1.9 | length 220.7
  Signal Layer 3 w40: J35.3@2610,3670 2660,3720 P1.9@2660,3870
VDDA_3V3_DUT: C76.2 C78.1 C79.1 C80.1 J21.1 J23.1 U7.1
VDDIO: C18.1 C19.1 C20.1 C23.1 C24.1 C25.1 J33.1 R75.2 R77.2 R105.2 R110.2 TP3.1 U2.18 U2.30 | length 1403.8
  Top Layer w8: v3(2356.69,1535) 2381,1535 2390.16,1525.84 U2.18@2390.16,1506.14 ; U2.30@2533.86,1630.16 2573.41,1630.16 v3(2575,1628.56)
  Top Layer w10: v2(2871.38,2999.95) 3070,3198.57 3070,3395 v2(3125,3450)
  Top Layer w15: R75.2@2494.53,1845 v2(2552,1845)
  Top Layer w22: v2(2540,1960) TP3.1@2540,2050 v2(2600,2050)
  Bottom Layer w10: C23.1@2345,1495 2345,1523.31 v3(2356.69,1535) C19.1@2386.38,1535 ; v2(2871.38,2999.95) R110.2@2900,2999.95
  Bottom Layer w15: C24.1@2548.62,1580 C20.1@2548.62,1620 2557.22,1628.6 v3(2575,1628.56)
  Bottom Layer w20: R77.2@2310,1974.96 2310,1975.75 2334.25,2000 2500,2000 v2(2540,1960) ; v2(2600,2050) 2601.13,2048.87 C18.1@2660,2048.87 C25.1@2660,1997.37
VDDIO_DUT: C86.2 J28.1 U8.1
VDDIO_EXT: J28.3 P1.13 | length 262.1
  Signal Layer 3 w40: P1.13@2860,3870 2860,3820 J28.3@3010,3670
VFX: J15.2 J26.1
XI: R89.2 R94.2 R95.1 U2.19 | length 192
  Top Layer w8: R89.2@2399.84,1454.96 v3(2399.84,1477) 2409.84,1487 U2.19@2409.84,1506.14
  Bottom Layer w10: v3(2399.84,1477) 2422.84,1500 R94.2@2487.01,1500 R95.1@2487.01,1540
XO: R86.2 U2.20 | length 55.3
  Top Layer w8: U2.20@2429.53,1506.14 2429.53,1487 2439.53,1477 R86.2@2439.53,1454.96
pads on no net: FID1.1 FID2.1 FID3.1 FID4.1 FID5.1 FID6.1 J3.MH1 J3.MH2 J14.29 J32.4 LBL1.0 SH1.0 SH2.0 SH3.0 SH4.0 SH5.0 SH6.0 SH7.0 SH8.0 SH9.0 SH10.0 SH11.0 SH12.0 SH13.0 U1.1 U1.2 U1.3 U1.4 U1.5 U1.6 U1.7 U1.8 U1.9 U1.10 U1.12 U1.13 U1.15 U1.16 U1.17 U1.27 U1.28 U1.29 U1.30 U1.31 U1.32 U1.33 U1.34 U1.35 U1.36 U1.41 U1.42 U1.43 U1.44 U1.45 U1.48 U1.51 U1.52 U1.53 U1.54 U1.55 U1.56 U1.57 U1.58 U1.59 U1.60 U1.72 U1.73 U1.74 U1.75 U1.77 U1.78 U1.79 U1.80 U2.49@2346.06,1586.06 U2.49@2346.06,1640 U2.49@2346.06,1693.94 U2.49@2400,1586.06 U2.49@2400,1640 U2.49@2400,1693.94 U2.49@2453.94,1586.06 U2.49@2453.94,1640 U2.49@2453.94,1693.94 U4.3@1743.56,1532.56 U4.8@1776.44,1532.56 U5.3@1743.56,1766.42 U5.8@1776.44,1766.42 U7.2 U7.5 U7.7@2021.61,3222.28 U7.7@2021.61,3257.72 U8.2 U8.5 U8.7@3112.28,3290 U8.7@3147.72,3290 U9.2 U9.6 U9.7 U10.11@2819.76,3190.16 U10.11@2819.76,3209.84 U10.11@2855.2,3200 U10.11@2904.8,3200 U10.11@2940.24,3190.16 U10.11@2940.24,3209.84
